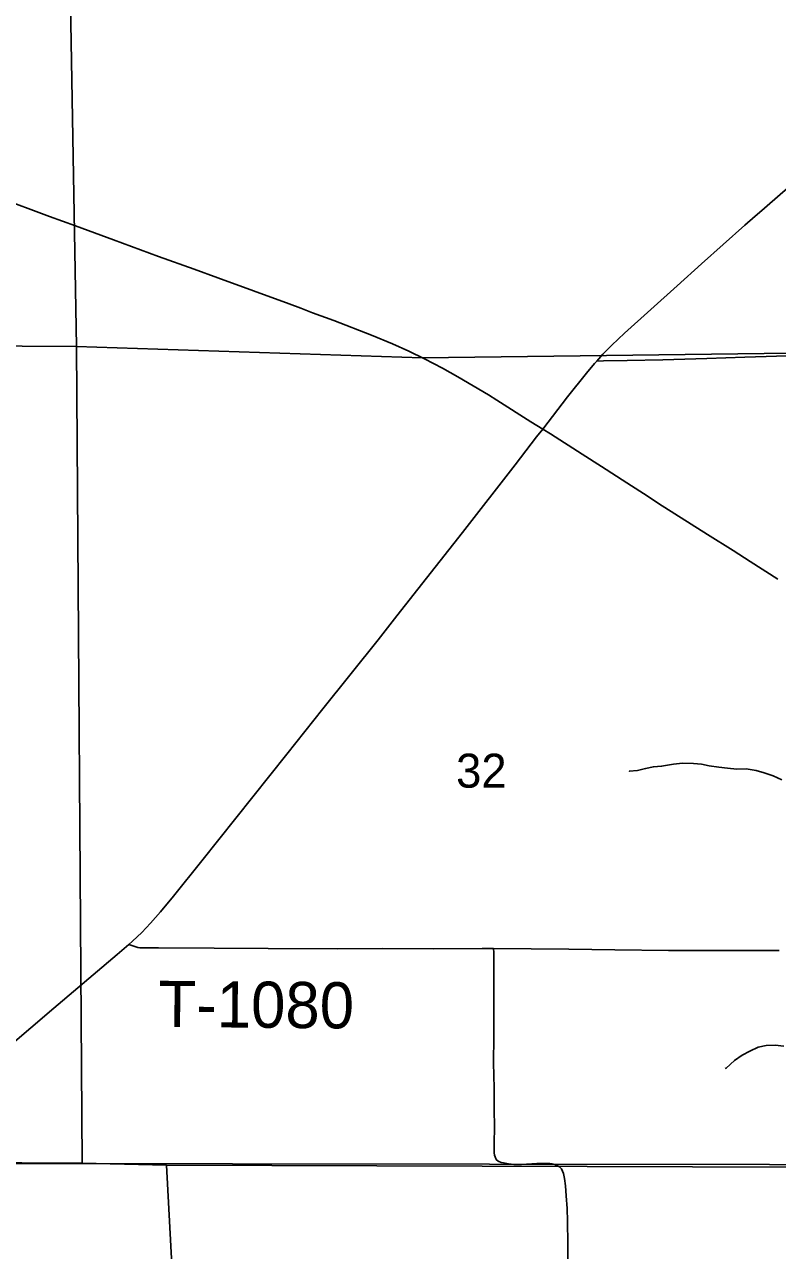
# Model space of a CAD drawing. Extents: x 1874609 to 2204689, y 815661 to 1281160.
# Drawn here: x 2049821 to 2054716, y 1056338 to 1064307 of the extents above; entities that cross this region are included whole.
import ezdxf

# ---------------------------------------------------------------- set-up
doc = ezdxf.new("R2010")
doc.units = 0
for name, color, linetype in [('GM_X_Minor_River', 7, 'Continuous'), ('GM_X_Section', 7, 'Continuous'), ('GM_X_Section_Text', 7, 'Continuous'), ('GM_X_State_Route', 7, 'Continuous'), ('GM_X_Township', 7, 'Continuous'), ('GM_X_Township_Road', 7, 'Continuous'), ('GM_X_Township_Road_Text', 7, 'Continuous'), ('GM_X_US_Route', 7, 'Continuous')]:
    doc.layers.add(name, color=color, linetype=linetype)

msp = doc.modelspace()

# ---------------------------------------------------------------- linework, layer by layer
at = {"layer": 'GM_X_Minor_River'}
for points in [[(2054744.1, 1059397.3), (2054688.4, 1059423.9), (2054630.5, 1059442.5), (2054576.7, 1059457.1), (2054512.8, 1059467.7), (2054450.8, 1059466.3), (2054390.9, 1059472.9), (2054334.9, 1059479.5), (2054273, 1059488.1), (2054221.1, 1059498.6), (2054169.2, 1059503.1), (2054099.2, 1059505.8), (2054039.2, 1059498.4), (2053963.1, 1059485.1), (2053909.1, 1059481.6), (2053859, 1059470.1), (2053806.9, 1059458.6), (2053752.9, 1059453.1), (2053754.9, 1059453.1)], [(2054757.4, 1057666.2), (2054701.5, 1057672.8), (2054643.5, 1057669.3), (2054589.4, 1057659.8), (2054537.2, 1057632.3), (2054487, 1057606.8), (2054436.7, 1057573.2), (2054382.3, 1057523.6), (2054376.3, 1057519.7)]]:
    msp.add_lwpolyline(points, dxfattribs=at)
at = {"layer": 'GM_X_Section'}
for points in [[(2050065.8, 1067532), (2050158.4, 1062213.2), (2044851.1, 1062246.7), (2044748.5, 1067571.4)], [(2055287, 1067524.1), (2055313.6, 1062177.1), (2052406, 1062140.9), (2050158.4, 1062213.2), (2050065.8, 1067532)], [(2044851.1, 1062246.7), (2050158.4, 1062213.2), (2050194.9, 1056904.2), (2045500, 1056931.9), (2044903.6, 1056945.9)], [(2055313.6, 1062177.1), (2055530.1, 1056876.8), (2050743.2, 1056892.2), (2050194.9, 1056904.2), (2050158.4, 1062213.2), (2052406, 1062140.9)], [(2050194.9, 1056904.2), (2050743.2, 1056892.2), (2051042.8, 1051308), (2045462.7, 1051564.8), (2045500, 1056931.9)], [(2055530.1, 1056876.8), (2055906.4, 1056868), (2056063, 1051515.5), (2051042.8, 1051308), (2050743.2, 1056892.2)]]:
    msp.add_lwpolyline(points, close=True, dxfattribs=at)
at = {"layer": 'GM_X_State_Route'}
for points in [[(2053189.8, 1061677.3), (2053113.4, 1061723.5), (2052892.5, 1061865), (2052836.9, 1061900.1), (2052639, 1062017), (2052538.6, 1062073.1), (2052422.1, 1062133.7), (2052318.6, 1062184), (2052213.6, 1062231), (2052077.2, 1062287.7), (2051832.1, 1062382.2), (2051693.4, 1062432.6), (2051617.3, 1062462.9), (2051540.5, 1062492), (2051077.9, 1062660.2), (2050923.8, 1062716.4), (2050692.1, 1062799.7), (2050399.2, 1062906.4), (2050153.4, 1062998.4), (2049983.7, 1063060), (2049644.7, 1063183.9)], [(2053541.6, 1062119.1), (2053584.7, 1062119.8), (2053738.3, 1062122.3), (2053971.4, 1062127.2), (2054257.2, 1062135.4), (2054503.2, 1062143.5), (2054847.6, 1062155.5)], [(2054718.6, 1060702.2), (2054538.4, 1060816.3), (2054427.9, 1060886.8), (2054261.5, 1060991.8), (2053943.3, 1061194.4), (2053874.9, 1061239.7), (2053736.2, 1061327.4), (2053570.9, 1061434.2), (2053446.6, 1061514.1), (2053239.6, 1061647.2), (2053189.8, 1061677.3)]]:
    msp.add_lwpolyline(points, dxfattribs=at)
at = {"layer": 'GM_X_Township'}
for points in [[(2071122.1, 1077956.3), (2071255.1, 1071443.9), (2071304.4, 1070159.8), (2071270.7, 1069576.7), (2071181.7, 1067473.1), (2071243.1, 1064399.7), (2071288.2, 1062148.4), (2071392.9, 1056914.6), (2063510.6, 1056885.7), (2061446.3, 1056888.3), (2059528.3, 1056890.6), (2058304.2, 1056892.2), (2052843.3, 1056898.9), (2047828.1, 1056905.1), (2047574.2, 1056905.4), (2045481.2, 1056908), (2044859.9, 1056908.1), (2044746.9, 1064387.8), (2044699.1, 1067550.3), (2044618.5, 1072885.8), (2044539, 1078146.3)], [(2045478.3, 1056323.1), (2045481.2, 1056908), (2047574.2, 1056905.4), (2047828.1, 1056905.1), (2052843.3, 1056898.9), (2058304.2, 1056892.2), (2059528.3, 1056890.6), (2061446.3, 1056888.3), (2063510.6, 1056885.7), (2071392.9, 1056914.6), (2071559.1, 1056912.2), (2071772.3, 1055613.7)]]:
    msp.add_lwpolyline(points, dxfattribs=at)
at = {"layer": 'GM_X_Township_Road'}
for points in [[(2050498.2, 1058326.8), (2050544.6, 1058311.4), (2050556.9, 1058307.8), (2050571.3, 1058305.4), (2050692.4, 1058305.2), (2051053.4, 1058303.5), (2051405.5, 1058301.6), (2051854, 1058299.3), (2052147.9, 1058301.5), (2052477, 1058299.3), (2052795.2, 1058301.4), (2052870.9, 1058300.8)], [(2052899.4, 1056919.3), (2052888, 1056930), (2052879.8, 1056946.1), (2052876.6, 1056956.4), (2052874.4, 1056972.5), (2052873.1, 1057021.4), (2052875.7, 1057152.2), (2052875.2, 1057243), (2052874.8, 1057339.6), (2052874.5, 1057394.8), (2052872.6, 1057472.4), (2052870.5, 1057560.2), (2052871.7, 1057723.7), (2052872.1, 1058018.2), (2052871.3, 1058165.4), (2052871.1, 1058226.4), (2052871, 1058274.7), (2052870.9, 1058300.8)], [(2052870.9, 1058300.8), (2053358.6, 1058296.9), (2053659, 1058292.5), (2054008.1, 1058288), (2054244.5, 1058288), (2054478.7, 1058288), (2054726.1, 1058287.9)], [(2053298.2, 1056881.9), (2053283.9, 1056890.5), (2053268.3, 1056896.4), (2053252.1, 1056900), (2053235.6, 1056902.1), (2053202.2, 1056903.7), (2053152.1, 1056902.8), (2053051.7, 1056897.1), (2053001.6, 1056897.6), (2052968.4, 1056900.8), (2052935.5, 1056906.6), (2052919.3, 1056910.6), (2052899.4, 1056919.3)], [(2053424.8, 1054672.5), (2053418.6, 1054791.9), (2053413.4, 1054890.1), (2053406.8, 1055021.1), (2053402.1, 1055119.2), (2053392.2, 1055348.6), (2053380.2, 1055610.7), (2053363.8, 1055954.8), (2053359.3, 1056064.5), (2053352.4, 1056233.3), (2053352.1, 1056380.9), (2053350.9, 1056528.5), (2053348, 1056610.5), (2053342.9, 1056692.3), (2053337.2, 1056757.7), (2053330.8, 1056806.4), (2053324.2, 1056838.4), (2053319, 1056854), (2053311, 1056868.7), (2053298.2, 1056881.9)]]:
    msp.add_lwpolyline(points, dxfattribs=at)
at = {"layer": 'GM_X_US_Route'}
for points in [[(2054570.3, 1063060.1), (2054614.8, 1063099), (2054751.2, 1063217.3), (2054854.3, 1063305.2), (2054939.2, 1063361.8), (2054993.9, 1063402.4), (2055111.9, 1063494.8), (2055265.2, 1063617), (2055415.8, 1063743.8), (2055489.2, 1063809.2), (2055598.7, 1063908.4), (2055807.5, 1064093.4), (2056040.6, 1064300.6), (2056187.4, 1064431.8)], [(2049711.5, 1057656.5), (2050011.1, 1057912), (2050424.3, 1058262.1), (2050498.2, 1058326.8), (2050523.2, 1058348.6), (2050582.9, 1058405.3), (2050639.8, 1058464.7), (2050705, 1058538.7), (2050788.8, 1058639.9), (2050973.9, 1058870.2), (2051525.5, 1059563.8), (2051760.3, 1059859.3), (2052119.1, 1060307.9), (2052240.5, 1060463), (2052434.5, 1060707.1), (2052667.9, 1061003.8), (2053010.7, 1061444.1), (2053150.4, 1061626.5), (2053189.8, 1061677.3), (2053351.4, 1061885.8), (2053473.5, 1062040.2), (2053526.5, 1062102.6), (2053541.6, 1062119.1), (2053581.7, 1062163), (2053639, 1062221.6), (2053721.8, 1062300.9), (2053891.9, 1062455.1), (2054062.9, 1062608.4), (2054222.2, 1062750.3), (2054503.6, 1063001.8), (2054570.3, 1063060.1)]]:
    msp.add_lwpolyline(points, dxfattribs=at)

# ---------------------------------------------------------------- texts
at = {"layer": 'GM_X_Section_Text'}
msp.add_text('32', height=221, rotation=0.00001, dxfattribs=at).set_placement((2052626.5, 1059346))
at = {"layer": 'GM_X_Township_Road_Text'}
msp.add_text('T-1080', height=300, rotation=359.53123, dxfattribs=at).set_placement((2050691, 1057791))

doc.saveas('drawing.dxf')
